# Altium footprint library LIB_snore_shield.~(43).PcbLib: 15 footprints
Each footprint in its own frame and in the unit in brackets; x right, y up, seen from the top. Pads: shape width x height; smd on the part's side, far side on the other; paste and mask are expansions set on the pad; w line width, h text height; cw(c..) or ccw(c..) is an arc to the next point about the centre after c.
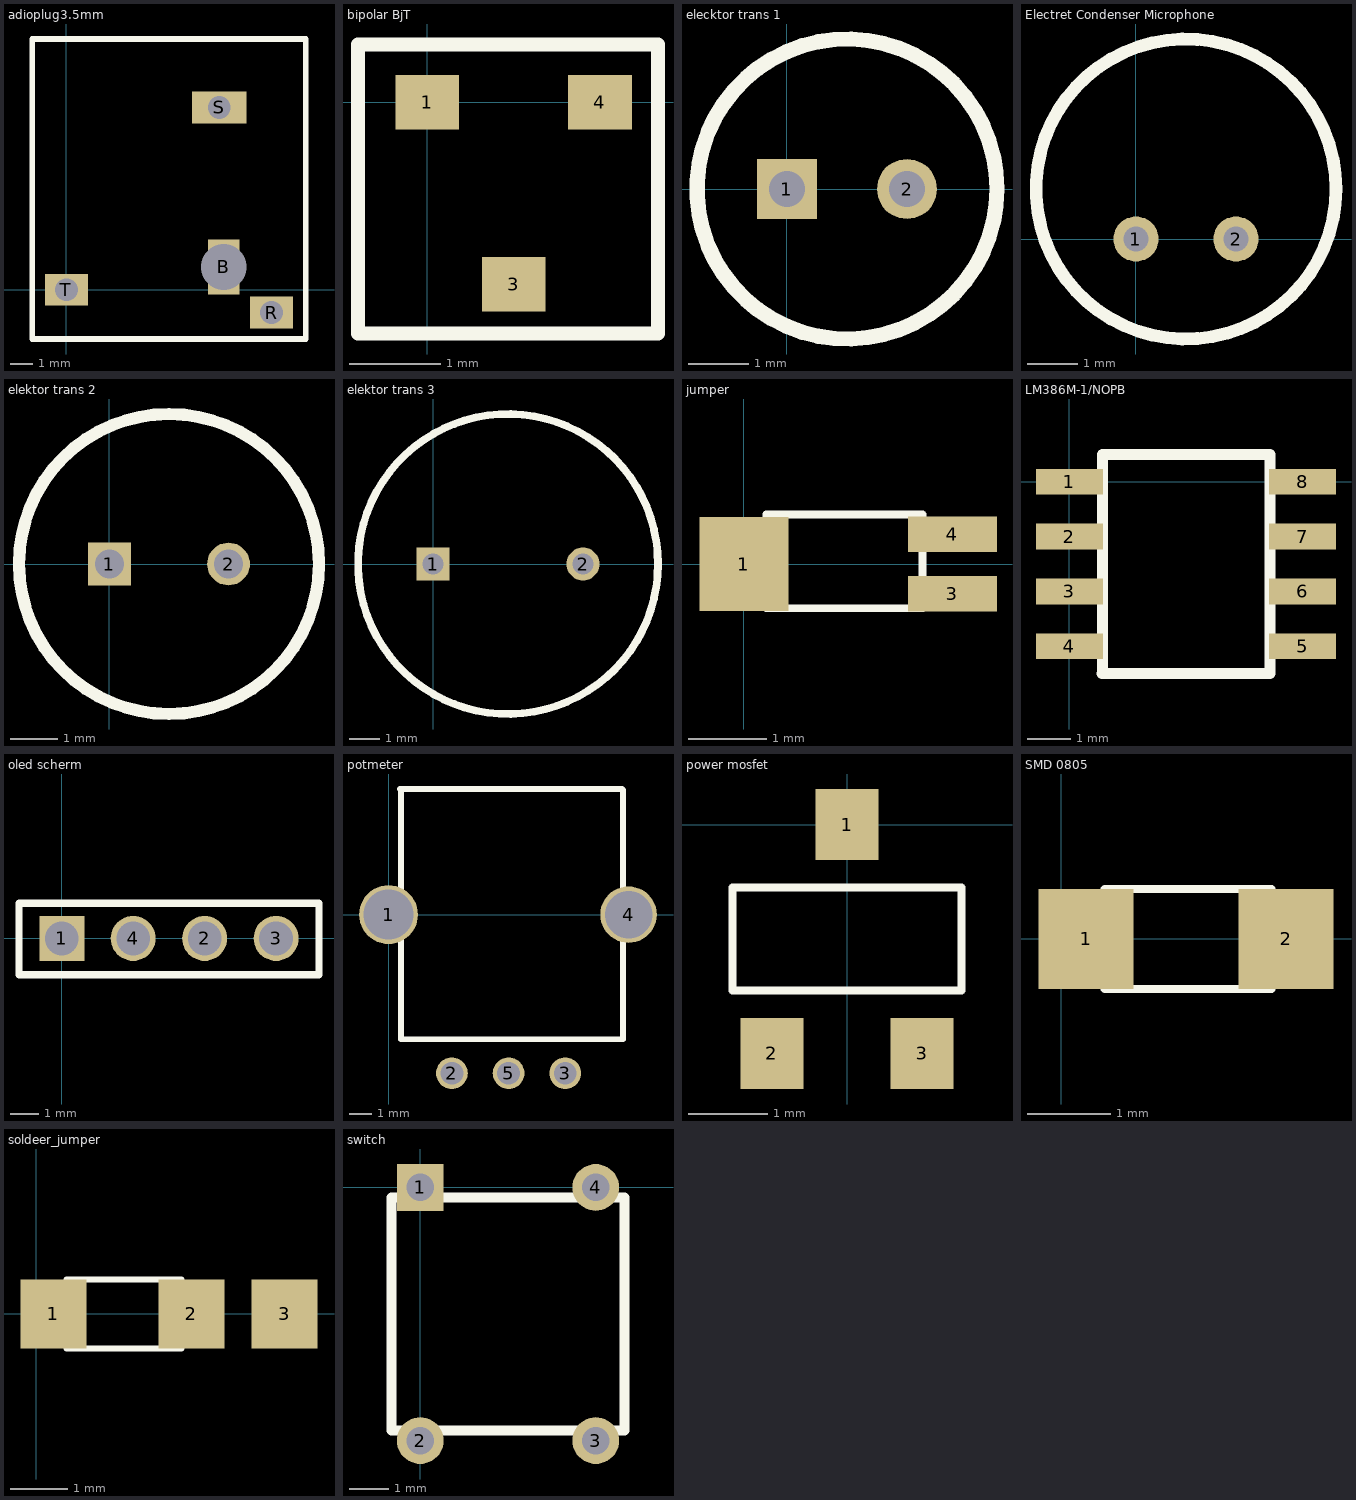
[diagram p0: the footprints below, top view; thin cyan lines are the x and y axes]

## adioplug3.5mm [mm]
pads (4):
  rect 1.4x2.4 hole 2 square: B(6.9,1)
  rect 1.9x1.4 hole 1 square: R(9,-1)
  rect 2.4x1.4 / inner rect 2.2x1.27 / far side rect 2.2x1.2 hole 1 square: S(6.7,8)
  rect 1.9x1.4 / inner rect 2.54x1.27 / far side rect 1.7x1.2 hole 1 square: T(0,0)
Top Overlay:
  lines w0.254: -1.5,-2.159 -1.5,11 10.5,11 10.5,-2.159 -1.5,-2.159

## bipolar BjT [mm]
pads (3):
  rect 0.7x0.6 smd: 1(0,0) 3(0.95,-2) 4(1.9,0)
Top Overlay:
  lines w0.154: -0.762,-2.54 2.538,-2.54 2.538,0.635 -0.762,0.635 -0.762,-2.54

## elecktor trans 1 [mm]
pads (2):
  rect 1x1 hole 0.6: 1(0,0)
  round 1 hole 0.6: 2(2,0)
Top Overlay:
  circle w0.254: c1,0 r2.5

## Electret Condenser Microphone [mm]
pads (2):
  round 0.9 hole 0.5: 1(0,0) 2(2,0)
Top Overlay:
  circle w0.254: c1,1 r3

## elektor trans 2 [mm]
pads (2):
  rect 0.9x0.9 hole 0.6: 1(0,0)
  round 0.9 hole 0.6: 2(2.5,0)
Top Overlay:
  circle w0.254: c1.25,0 r3.15

## elektor trans 3 [mm]
pads (2):
  rect 1.1x1.1 hole 0.7: 1(0,0)
  round 1.1 hole 0.7: 2(5,0)
Top Overlay:
  circle w0.254: c2.5,0 r5

## jumper [mm]
pads (3):
  rect 1.14x1.2 smd: 1(0,0)
  rect 1.14x0.45 smd: 3(2.667,-0.381) 4(2.667,0.381)
Top Overlay:
  lines w0.1: 0.286,-0.565 2.286,-0.565 2.286,0.635 0.286,0.635 0.286,-0.565

## LM386M-1/NOPB [mm]
pads (8):
  rect 1.55x0.6 smd: 1(0,0) 2(0,-1.27) 3(0,-2.54) 4(0,-3.81) 5(5.4,-3.81) 6(5.4,-2.54) 7(5.4,-1.27) 8(5.4,0)
Top Overlay:
  lines w0.254: 0.75,-4.445 4.65,-4.445 4.65,0.635 0.762,0.635 0.762,-4.445

## oled scherm [mm]
pads (4):
  rect 1.6x1.6 hole 1.2: 1(0,0)
  round 1.6 hole 1.2: 2(5.08,0) 3(7.62,0) 4(2.54,0)
Top Overlay:
  lines w0.254: -1.52,-1.29 -1.52,1.25 9.144,1.25 9.144,-1.29 -1.52,-1.29

## PCBComponent_1 [mm]

## potmeter [mm]
pads (5):
  round 2.6 / inner round 2.5 / far side round 2.5 hole 2.2: 1(0,0)
  round 1.4 hole 1: 2(2.8,-7) 5(5.3,-7)
  round 1.4 / inner oval 1.4x0.064 / far side round 1.4 hole 1: 3(7.8,-7)
  round 2.5 / inner oval 2.5x0.064 / far side round 2.5 hole 2.1: 4(10.6,0)
Top Overlay:
  lines w0.254: 0.508,5.549 10.308,5.549 ; 0.55,5.5 0.55,-5.5 10.35,-5.5 10.35,5.5

## power mosfet [mm]
pads (3):
  rect 0.8x0.9 smd: 1(0,0) 2(-0.95,-2.9) 3(0.95,-2.9)
Top Overlay:
  lines w0.1: -1.45,-2.1 -1.45,-0.8 1.45,-0.8 1.45,-2.1 -1.45,-2.1

## SMD 0805 [mm]
pads (2):
  rect 1.14x1.2 smd: 1(0.3,0) 2(2.7,0)
Top Overlay:
  lines w0.1: 0.525,-0.6 0.525,0.6 2.525,0.6 2.525,-0.6 0.525,-0.6

## soldeer_jumper [mm]
pads (3):
  rect 1.14x1.2 smd: 1(0.3,0) 2(2.7,0) 3(4.318,0)
Top Overlay:
  lines w0.1: 0.525,-0.6 2.525,-0.6 2.525,0.6 0.525,0.6 0.525,-0.6

## switch [mm]
pads (4):
  rect 1.2x1.2 hole 0.71: 1(0,0)
  round 1.2 hole 0.71: 2(0,-6.5) 3(4.5,-6.5) 4(4.5,0)
Top Overlay:
  lines w0.254: -0.745,-6.245 -0.745,-0.255 5.245,-0.255 5.245,-6.245 -0.745,-6.245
